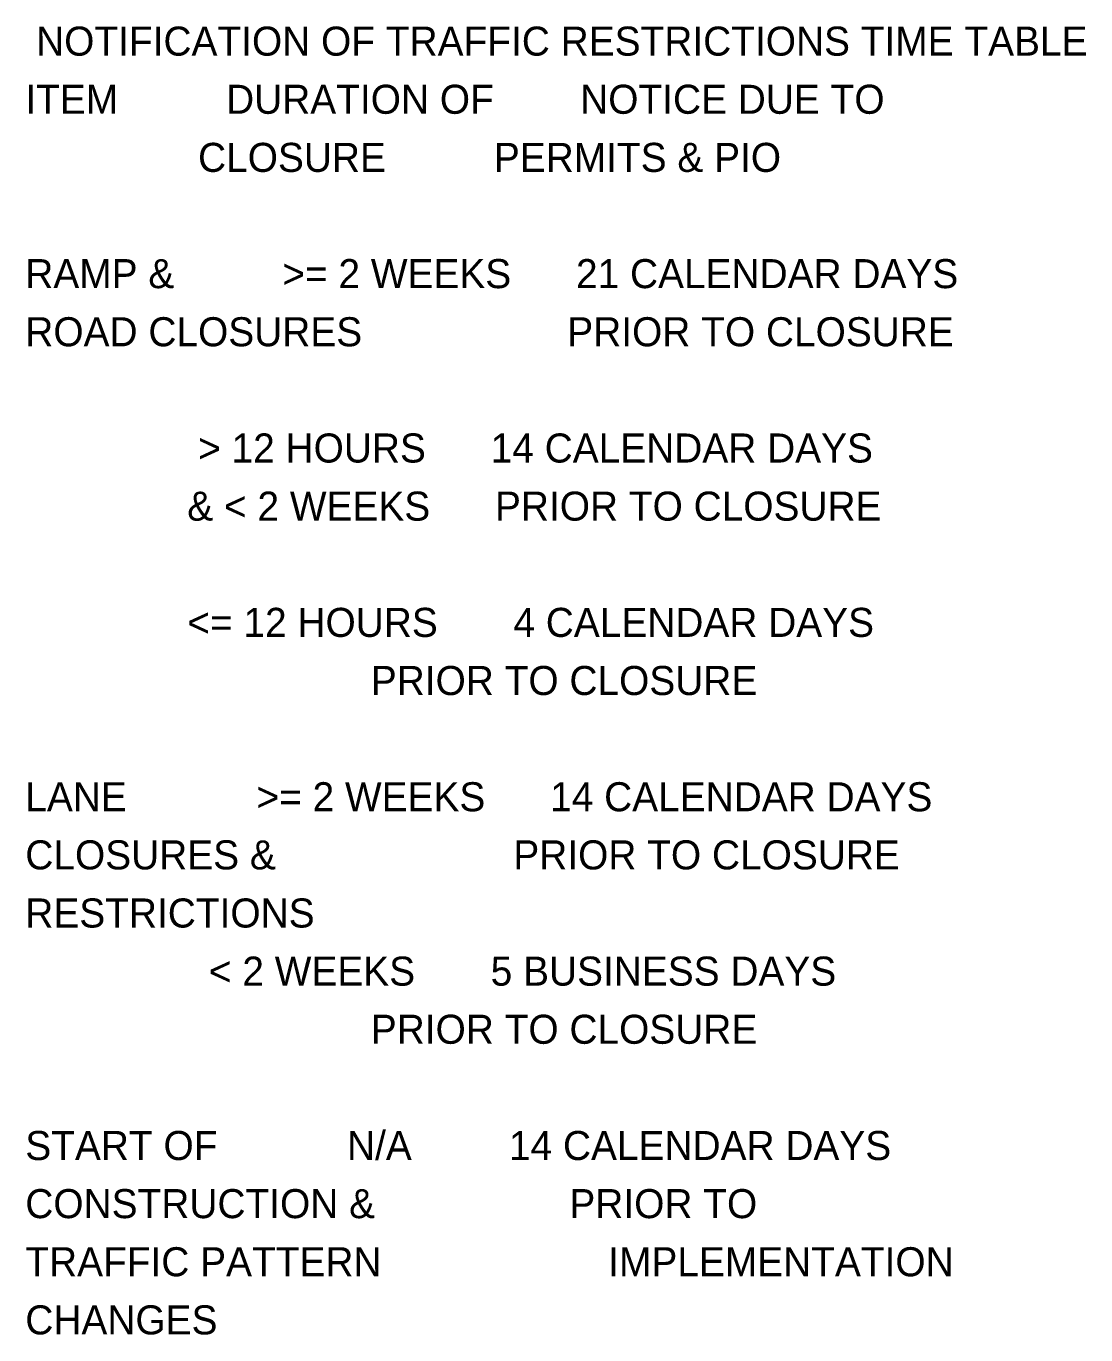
# Model space of a CAD drawing. Extents: x 0 to 34, y -13.7 to 22.
# Drawn here: x 17.65 to 22.76, y -13.7 to -7.39 of the extents above; entities that cross this region are included whole.
import ezdxf

# ---------------------------------------------------------------- set-up
doc = ezdxf.new("R2010")
doc.units = 0
doc.layers.add('SH_Text', color=7, linetype='Continuous')

msp = doc.modelspace()

# ---------------------------------------------------------------- texts
at = {"layer": 'SH_Text'}
for s, p in [(' NOTIFICATION OF TRAFFIC RESTRICTIONS TIME TABLE', (17.6471, -7.5335)), ('ITEM          DURATION OF        NOTICE DUE TO', (17.6471, -7.8135)), ('                CLOSURE          PERMITS & PIO', (17.6471, -8.0935)), ('RAMP &          >= 2 WEEKS      21 CALENDAR DAYS', (17.6471, -8.6535)), ('ROAD CLOSURES                   PRIOR TO CLOSURE', (17.6471, -8.9335)), ('                > 12 HOURS      14 CALENDAR DAYS', (17.6471, -9.4935)), ('               & < 2 WEEKS      PRIOR TO CLOSURE', (17.6471, -9.7735)), ('               <= 12 HOURS       4 CALENDAR DAYS', (17.6471, -10.3335)), ('                                PRIOR TO CLOSURE', (17.6471, -10.6135)), ('LANE            >= 2 WEEKS      14 CALENDAR DAYS', (17.6471, -11.1735)), ('CLOSURES &                      PRIOR TO CLOSURE', (17.6471, -11.4535)), ('RESTRICTIONS', (17.6471, -11.7335)), ('                 < 2 WEEKS       5 BUSINESS DAYS', (17.6471, -12.0135)), ('                                PRIOR TO CLOSURE', (17.6471, -12.2935)), ('START OF            N/A         14 CALENDAR DAYS', (17.6471, -12.8535)), ('CONSTRUCTION &                  PRIOR TO', (17.6471, -13.1335)), ('TRAFFIC PATTERN                     IMPLEMENTATION', (17.6471, -13.4135)), ('CHANGES', (17.6471, -13.6935))]:
    msp.add_text(s, height=0.14, dxfattribs=at).set_placement(p)

doc.saveas('drawing.dxf')
